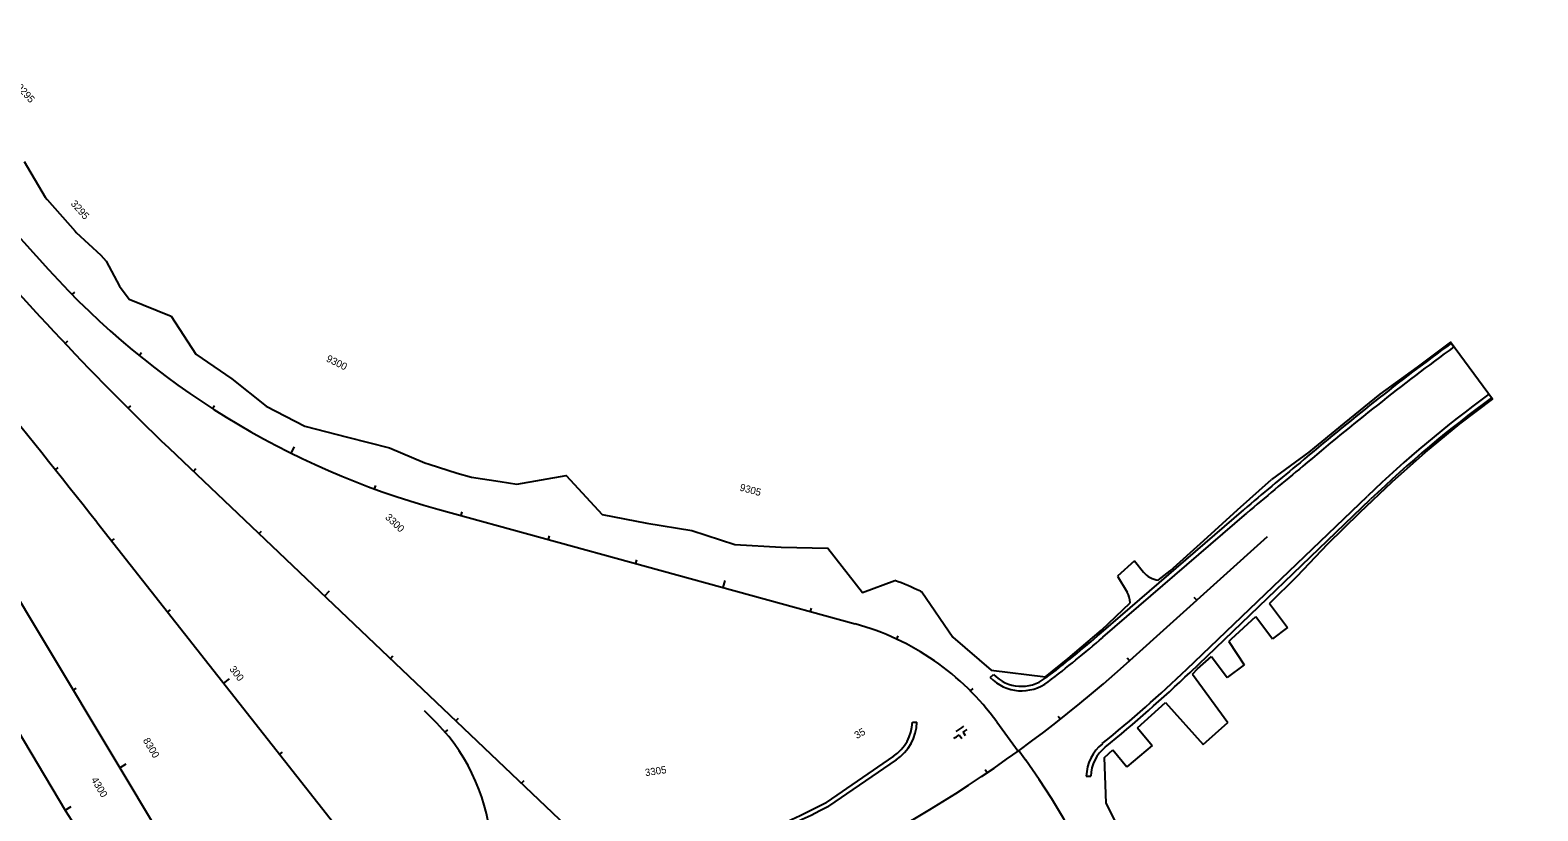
# Model space of a CAD drawing. Extents: x -5665 to 1997148, y 4 to 827579.
# Drawn here: x 1963763 to 1965427, y 804758 to 805620 of the extents above; entities that cross this region are included whole.
import ezdxf

# ---------------------------------------------------------------- set-up
doc = ezdxf.new("R2010")
doc.units = 0
for name, color, linetype in [('RD_HC_CL_Rel', 7, 'Continuous'), ('RD_HC_Data_Tic_Rel', 7, 'Continuous'), ('RD_HC_TX_Rel_Sta50', 7, 'Continuous'), ('RD_PD_CstnLmt', 7, 'Continuous'), ('RD_PD_SW', 7, 'Continuous')]:
    doc.layers.add(name, color=color, linetype=linetype)

msp = doc.modelspace()

# ---------------------------------------------------------------- linework, layer by layer
at = {"layer": 'RD_HC_CL_Rel'}
for p, q in [((1963334.8, 805851.3), (1963783, 805355.8)), ((1963522.1, 805228.1), (1963801.8, 804757.9)), ((1963923.8, 805151.2), (1964383.9, 804713.4)), ((1964212.7, 805091.2), (1964673.5, 804964.5)), ((1963836.3, 805076.9), (1966419.9, 801796.5)), ((1963703.7, 805069), (1963926.3, 804698.1)), ((1964972.8, 804920.7), (1965128.4, 805061)), ((1964197.5, 804868.8), (1964204.7, 804861.9)), ((1964829.6, 804856.2), (1964853.1, 804823.8)), ((1964853.9, 804824.4), (1964861.6, 804813.8))]:
    msp.add_line(p, q, dxfattribs=at)
for centre, radius, start, end in [((1954834, 797986.6), 11459.2, 38.22442, 42.13195), ((1966152.9, 807494.2), 3234, 220.0296, 226.4277), ((1964451.9, 805960.9), 902, 222.1319, 254.6189), ((1964597.5, 804688.2), 286.5, 35.8953, 74.6189), ((1964013.2, 805984.2), 1432.4, 290.3874, 312.0581), ((1964054.4, 804703.9), 218, 325.8435, 46.4277), ((1964278.7, 804391.2), 720, 3.3169, 35.9381), ((1964068.2, 804916.4), 310, 210.7484, 246.7893)]:
    msp.add_arc(centre, radius, start, end, dxfattribs=at)
at = {"layer": 'RD_HC_Data_Tic_Rel'}
for p, q in [((1963809.1, 805328.1), (1963812, 805330.9)), ((1963801.3, 805274.2), (1963804.2, 805276.9)), ((1963883.1, 805260.9), (1963885.6, 805264)), ((1963871, 805202.5), (1963873.9, 805205.4)), ((1963964, 805202.3), (1963966.2, 805205.6)), ((1964051, 805152.9), (1964054.5, 805160.1)), ((1963790.6, 805134.5), (1963793.7, 805137)), ((1963942.9, 805133), (1963945.7, 805135.9)), ((1964142.8, 805113.5), (1964144.2, 805117.3)), ((1964238.4, 805084.2), (1964239.4, 805088)), ((1963852.6, 805056.1), (1963855.8, 805058.5)), ((1964015.4, 805064.1), (1964018.1, 805067)), ((1964334.8, 805057.6), (1964335.9, 805061.5)), ((1964431.2, 805031.1), (1964432.3, 805035)), ((1964527.6, 805004.6), (1964529.8, 805012.3)), ((1964087.8, 804995.1), (1964093.3, 805000.9)), ((1965050.3, 804990.6), (1965047.6, 804993.6)), ((1963914.5, 804977.5), (1963917.7, 804980)), ((1964624.1, 804978.1), (1964625.1, 804981.9)), ((1964719.2, 804947.6), (1964720.9, 804951.3)), ((1964160.3, 804926.2), (1964163, 804929.1)), ((1964976.1, 804923.6), (1964973.4, 804926.6)), ((1963810.3, 804891.4), (1963813.7, 804893.4)), ((1963976.4, 804899), (1963982.7, 804903.9)), ((1964800.5, 804890.4), (1964803.4, 804893.2)), ((1964232.7, 804857.3), (1964235.5, 804860.2)), ((1964899.7, 804859), (1964897.3, 804862.2)), ((1964220.8, 804844.9), (1964223.8, 804847.4)), ((1963861.8, 804805.6), (1963868.6, 804809.7)), ((1964038.3, 804820.4), (1964041.4, 804822.9)), ((1964819.1, 804799.9), (1964816.8, 804803.2)), ((1964305.2, 804788.4), (1964307.9, 804791.3)), ((1963801.3, 804758.7), (1963808.2, 804762.8))]:
    msp.add_line(p, q, dxfattribs=at)
at = {"layer": 'RD_PD_CstnLmt'}
for p, q in [((1965095.2, 805090.2), (1965133, 805123.9)), ((1965058.2, 805056.4), (1965095.2, 805090.2)), ((1965021.1, 805023), (1965058.2, 805056.4)), ((1964981.6, 805033.9), (1964962.9, 805017)), ((1964981.6, 805033.9), (1964991.7, 805021.6)), ((1964962.9, 805017), (1964973.4, 804999.3)), ((1965007.8, 805012.6), (1965021.1, 805023)), ((1964745.4, 805000.5), (1964746.8, 804999.9)), ((1964945.4, 804957.6), (1964976.9, 804987.8)), ((1965130.6, 804986.9), (1965150.6, 804960.3)), ((1965115.5, 804972.6), (1965134, 804947.9)), ((1965150.6, 804960.3), (1965134, 804947.9)), ((1964908.6, 804926), (1964945.4, 804957.6)), ((1965085.6, 804945.1), (1965102.8, 804919.3)), ((1964883.5, 804906), (1964908.6, 804926)), ((1965066.6, 804928.3), (1965083.9, 804905.2)), ((1965045.5, 804908.8), (1965051.3, 804914.8)), ((1965045.5, 804908.8), (1965084.7, 804855.6)), ((1965102.8, 804919.3), (1965083.9, 804905.2)), ((1964984.8, 804849.7), (1965015.7, 804877.6)), ((1965015.7, 804877.6), (1965057.6, 804831.2)), ((1964984.8, 804849.7), (1965001.2, 804830.1)), ((1965057.6, 804831.2), (1965084.7, 804855.6)), ((1964948.5, 804817), (1964957.6, 804825.2)), ((1964957.6, 804825.2), (1964973.1, 804806.7)), ((1965001.2, 804830.1), (1964973.1, 804806.7))]:
    msp.add_line(p, q, dxfattribs=at)
for points in [[(1963756.1, 805475.1), (1963779.2, 805435.8), (1963781.5, 805433), (1963812.3, 805398.3), (1963813.5, 805396.8), (1963840.9, 805371.8), (1963840.9, 805371.8), (1963846.5, 805364.9), (1963861.2, 805337.6), (1963872.1, 805323), (1963918.3, 805304.3), (1963945.7, 805262.2), (1963985.2, 805235.1), (1964023.1, 805205), (1964065.9, 805182.9), (1964113, 805170.7), (1964159.4, 805158.9), (1964198.4, 805142.3), (1964198.5, 805142.3), (1964203.3, 805140.7), (1964233.9, 805130.9), (1964250, 805126.5), (1964281.4, 805121.6), (1964299.8, 805118.9), (1964354.2, 805128.3), (1964394.2, 805085.1), (1964443.5, 805075.6), (1964493.1, 805067.7), (1964540.7, 805052), (1964591.8, 805049.3), (1964643.3, 805048), (1964681.6, 804998.9), (1964717.2, 805012.3)], [(1965130.6, 804986.9), (1965161.1, 805017), (1965194.9, 805053), (1965230.2, 805087.5), (1965266.1, 805121.3), (1965302.9, 805154.1), (1965340.9, 805185.5), (1965376.8, 805212.5), (1965330.5, 805275.6), (1965293.6, 805247.9), (1965252.6, 805218), (1965213.2, 805186.1), (1965174.1, 805153.9), (1965133, 805123.9)], [(1964746.8, 804999.9), (1964781.3, 804949.6), (1964823.6, 804913.3), (1964883.5, 804906)], [(1965085.6, 804945.1), (1965088.8, 804947.9), (1965115.5, 804972.6)], [(1965051.3, 804914.8), (1965066.6, 804928.3)], [(1965224.5, 803730), (1965197.9, 803769), (1965174.7, 803809.3), (1965150, 803848.5), (1965131.6, 803891), (1965114.1, 803933.9), (1965097.9, 803977.3), (1965084.8, 804021.9), (1965073.5, 804067.1), (1965065.3, 804113.2), (1965043.4, 804160.3), (1965043.1, 804210.4), (1965040.7, 804260.4), (1965036.6, 804310.2), (1965034.2, 804360.1), (1965032.4, 804410.1), (1965031.1, 804461.4), (1965028, 804514), (1965021.9, 804566.7), (1965011.4, 804618.9), (1964995.7, 804670), (1964974.1, 804718.8), (1964950.2, 804766.5), (1964948.5, 804817)]]:
    msp.add_lwpolyline(points, dxfattribs=at)
for centre, radius, start, end in [((1964597.5, 804688.2), 345.5, 64.6623, 69.7279), ((1965011, 805037.4), 25, 219.3511, 262.6705), ((1964952, 804986.5), 25, 3.0273, 30.8982)]:
    msp.add_arc(centre, radius, start, end, dxfattribs=at)
at = {"layer": 'RD_PD_SW'}
for p, q in [((1965331.3, 805274.5), (1965334.2, 805270.5)), ((1965375.6, 805214.1), (1965372.7, 805218.1)), ((1965039.5, 804914.4), (1965238.8, 805105.6)), ((1965043, 804910.8), (1965242.2, 805102)), ((1964944.7, 804954.5), (1965102.3, 805090.4)), ((1964946.7, 804949.6), (1965105.6, 805086.7)), ((1964822.5, 804905.1), (1964826.1, 804908.6)), ((1964736.5, 804855.8), (1964741.5, 804855.8)), ((1964788.2, 804841.8), (1964790.9, 804838)), ((1964792.4, 804844.7), (1964794.8, 804841.2)), ((1964715.7, 804818.3), (1964641.3, 804767.3)), ((1964718.6, 804814.2), (1964643.9, 804763)), ((1964928.4, 804796.3), (1964933.4, 804796.1))]:
    msp.add_line(p, q, dxfattribs=at)
for centre, radius, start, end in [((1967047.5, 802933.9), 2902.4, 126.2503, 130.4535), ((1967047.5, 802933.9), 2897.4, 126.2503, 130.4551), ((1966156.8, 804148.8), 1326, 126.2503, 133.812), ((1966156.8, 804148.8), 1321, 126.2503, 133.812), ((1966999.3, 802891.6), 2904, 129.188, 130.7851), ((1966999.3, 802891.6), 2899, 129.1864, 130.7851), ((1964037.9, 806004.3), 1387.3, 307.543, 310.8192), ((1964037.9, 806004.3), 1392.3, 307.543, 310.751), ((1964857, 804938.5), 43, 223.9559, 307.543), ((1964013.2, 805984.2), 1482.4, 308.9999, 313.812), ((1964013.2, 805984.2), 1487.4, 308.9999, 313.812), ((1964857, 804938.5), 48, 223.9559, 307.543), ((1964688.6, 804857.9), 48, 304.4417, 357.4456), ((1964688.6, 804857.9), 53, 304.4417, 357.7496), ((1964013.2, 805984.2), 1380.4, 303.851, 304.1545), ((1964013.2, 805984.2), 1375.4, 304.1271, 304.5601), ((1964013.2, 805984.2), 1380.4, 304.362, 304.5961), ((1964976.4, 804794.8), 48, 128.9999, 178.2847), ((1964976.4, 804794.8), 43, 128.9999, 178.2847), ((1964013.2, 805984.2), 1369.4, 290.1469, 297.2985), ((1964013.2, 805984.2), 1374.4, 290.1469, 297.3115)]:
    msp.add_arc(centre, radius, start, end, dxfattribs=at)

# ---------------------------------------------------------------- texts
at = {"layer": 'RD_HC_TX_Rel_Sta50'}
for s, rotation, p in [('9295', 312.1319, (1963746.8, 805556.8)), ('3295', 311.58, (1963807, 805428.1)), ('9300', 333.6092, (1964088.8, 805254.8)), ('9305', 344.6189, (1964545.3, 805111.8)), ('3300', 316.4277, (1964154, 805081.3)), ('300', 308.2244, (1963982.1, 804914.3)), ('35', 30.2345, (1964675.3, 804837.1)), ('8300', 300.9813, (1963886.9, 804835.7)), ('4300', 300.7484, (1963829.7, 804792.3)), ('3305', 8.7155, (1964442, 804796.1))]:
    msp.add_text(s, height=8, rotation=rotation, dxfattribs=at).set_placement(p)

doc.saveas('drawing.dxf')
